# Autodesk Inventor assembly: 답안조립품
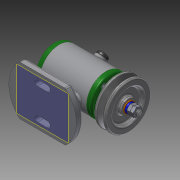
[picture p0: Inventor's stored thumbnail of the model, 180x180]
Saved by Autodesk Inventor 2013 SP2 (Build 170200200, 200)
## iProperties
Created: 2022-02
Part Number: 답안조립품
Document SubType Name: Assembly
Designer: a
Author: a
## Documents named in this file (14)
- C:\Users\a\Desktop\720206V1020\답안조립품.iam
- C:\Users\a\Desktop\720206V1020\본체.ipt
- C:\Users\a\Desktop\720206V1020\V벨트풀리.ipt
- C:\Users\a\Desktop\720206V1020\고무 캡.ipt
- C:\Users\a\Desktop\720206V1020\너트 M8.ipt
- C:\Users\a\Desktop\720206V1020\뒤커버.ipt
- C:\Users\a\Desktop\720206V1020\베어링 6002.ipt
- C:\Users\a\Desktop\720206V1020\볼트 M4 x 10.ipt
- C:\Users\a\Desktop\720206V1020\스프링와셔 8.ipt
- C:\Users\a\Desktop\720206V1020\앞커버.ipt
- C:\Users\a\Desktop\720206V1020\오일 실 15 x 25 x 7.ipt
- C:\Users\a\Desktop\720206V1020\축.ipt
- C:\Users\a\Desktop\720206V1020\키 3 x 3 x 12.ipt
- C:\Users\a\Desktop\720206V1020\평와셔 8 x 17.ipt
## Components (2 placed, 2 different names)
1. V벨트풀리:1
2. 고무 캡:1
